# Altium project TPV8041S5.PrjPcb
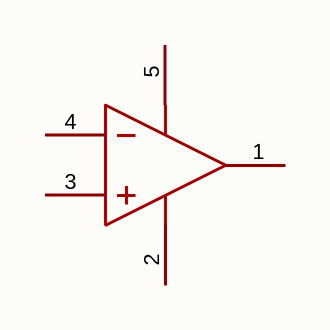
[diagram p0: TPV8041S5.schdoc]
1 sheet, 1 parts. Net scope: global (net labels, ports and power ports of the same name join across sheets).

## Sheet TPV8041S5.schdoc
size 127 x 101 mm

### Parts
U?  tpv8041s5  [SOT-23-5_L2.9-W1.6-P0.95-LS2.8-BR]  (value not drawn)

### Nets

Not connected (* = marked no-connect by the designer): U? 1(OUT) 2(VSS) 3(IN+) 4(IN-) 5(VDD)

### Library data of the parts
U? = tpv8041s5: 放大器数:1;轨到轨:轨到轨输入,轨到轨输出;增益带宽积(GBW):14.5kHz;输入失调电压(Vos):3mV;压摆率(SR):6V/ms;输入偏置电流(Ib):1pA;; Manufacturer: TECH PUBLIC(台舟); AddInBom: yes; ModelId: 7ba65df16e7b4570af156e925f9c37fe; ModelTransform: 114.173,114.173,0,90,0,0,0,0,0; Number of Channels: 1; Maximum Power Supply Range (Vdd-Vss): 7.5V; Vos - Input Offset Voltage: 3mV; Input Offset Voltage Drift(Vos TC): 2.5uV/℃; Slew Rate: 6V/ms; Ib - Input Bias Current: 1pA; Input Voltage Noise Density: 30nV/√Hz@1kHz; Common Mode Rejection Ratio(CMRR): 84dB; Quiescent Current: 700nA; Output Current: 20mA; Single supply: 1.4V~5.5V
